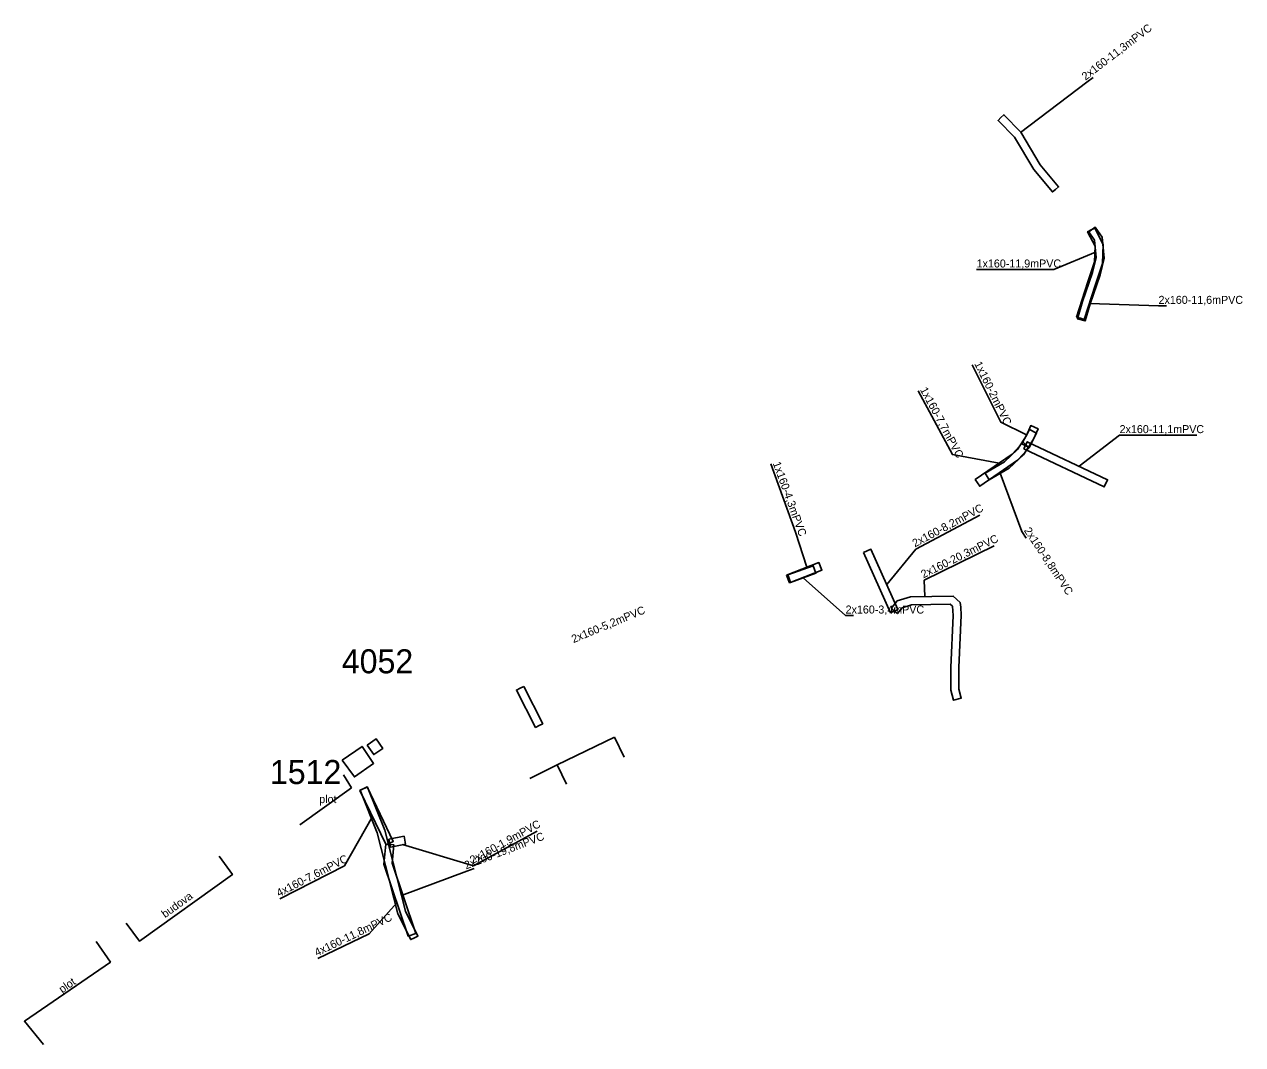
# Model space of a CAD drawing. Extents: x -743932 to -743780, y -1055899 to -1055771.
import ezdxf

# ---------------------------------------------------------------- set-up
doc = ezdxf.new("R2010")
doc.units = 0
for name, color, linetype in [('Chránička', 7, 'Continuous'), ('ST_CHRANICKA_POPIS', 7, 'Continuous'), ('ST_OBECNA_STAVBA', 7, 'Continuous'), ('ST_OBECNA_STAVBA_POPIS', 7, 'Continuous'), ('ST_TRAFOSTANICE_POPIS', 7, 'Continuous'), ('TS_RS_R', 7, 'Continuous')]:
    doc.layers.add(name, color=color, linetype=linetype)

msp = doc.modelspace()

# ---------------------------------------------------------------- linework, layer by layer
at = {"layer": 'Chránička'}
for points in [[(-743803.15, -1055791.87), (-743803.534, -1055792.19), (-743805.869, -1055789.39), (-743808.279, -1055785.346), (-743810.319, -1055783.248), (-743809.96, -1055782.9), (-743809.601, -1055782.552), (-743807.481, -1055784.734), (-743805.051, -1055788.81), (-743802.766, -1055791.55), (-743803.15, -1055791.87)], [(-743800.03, -1055807.96), (-743800.507, -1055807.809), (-743799.116, -1055803.415), (-743798.287, -1055800.929), (-743798.205, -1055798.952), (-743799.134, -1055797.149), (-743798.69, -1055796.92), (-743798.246, -1055796.691), (-743797.195, -1055798.728), (-743797.293, -1055801.111), (-743798.164, -1055803.725), (-743799.553, -1055808.111), (-743800.03, -1055807.96)], [(-743799.006, -1055797.151), (-743798.177, -1055796.589), (-743797.326, -1055797.844), (-743797.065, -1055800.454), (-743797.562, -1055802.541), (-743798.835, -1055806.162), (-743799.451, -1055808.299), (-743800.411, -1055808.021), (-743799.788, -1055805.858), (-743798.521, -1055802.259), (-743798.078, -1055800.386), (-743798.297, -1055798.196), (-743799.006, -1055797.151)], [(-743811.7, -1055827.72), (-743811.954, -1055827.289), (-743809.541, -1055825.867), (-743807.907, -1055824.347), (-743806.783, -1055822.594), (-743806.249, -1055821.361), (-743805.79, -1055821.56), (-743805.331, -1055821.759), (-743805.897, -1055823.066), (-743807.133, -1055824.993), (-743808.939, -1055826.673), (-743811.446, -1055828.151), (-743811.7, -1055827.72)], [(-743806.393, -1055821.829), (-743805.507, -1055822.293), (-743806.457, -1055824.103), (-743807.343, -1055823.639), (-743806.393, -1055821.829)], [(-743807.185, -1055823.449), (-743806.449, -1055824.128), (-743807.898, -1055825.698), (-743812.614, -1055828.931), (-743813.18, -1055828.106), (-743808.556, -1055824.938), (-743807.185, -1055823.449)], [(-743807.113, -1055824.282), (-743806.687, -1055823.378), (-743796.637, -1055828.118), (-743797.063, -1055829.022), (-743807.113, -1055824.282)], [(-743827.126, -1055837.215), (-743826.214, -1055836.805), (-743822.834, -1055844.315), (-743823.746, -1055844.725), (-743827.126, -1055837.215)], [(-743836.747, -1055840.055), (-743832.707, -1055838.465), (-743832.341, -1055839.395), (-743836.381, -1055840.985), (-743836.747, -1055840.055)], [(-743836.44, -1055840.47), (-743836.608, -1055839.999), (-743833.408, -1055838.859), (-743833.24, -1055839.33), (-743833.072, -1055839.801), (-743836.272, -1055840.941), (-743836.44, -1055840.47)], [(-743823.681, -1055844.208), (-743822.915, -1055843.248), (-743821.28, -1055842.738), (-743815.929, -1055842.642), (-743815.07, -1055843.456), (-743814.98, -1055844.053), (-743814.919, -1055845.048), (-743815.23, -1055851.583), (-743815.24, -1055854.272), (-743814.928, -1055855.385), (-743815.892, -1055855.655), (-743816.24, -1055854.408), (-743816.23, -1055851.557), (-743815.921, -1055845.072), (-743816.03, -1055843.924), (-743816.311, -1055843.658), (-743821.14, -1055843.742), (-743822.325, -1055844.112), (-743822.899, -1055844.832), (-743823.681, -1055844.208)], [(-743869.59, -1055853.93), (-743867.21, -1055858.6), (-743867.66, -1055858.83), (-743868.11, -1055859.06), (-743870.49, -1055854.39), (-743870.04, -1055854.16), (-743869.59, -1055853.93)], [(-743890.051, -1055866.916), (-743889.149, -1055866.484), (-743885.879, -1055873.294), (-743886.781, -1055873.726), (-743890.051, -1055866.916)], [(-743883.25, -1055885.33), (-743883.697, -1055885.553), (-743885.301, -1055882.336), (-743887.896, -1055872.206), (-743890.034, -1055866.866), (-743889.57, -1055866.68), (-743889.106, -1055866.494), (-743886.944, -1055871.894), (-743884.359, -1055881.984), (-743882.803, -1055885.107), (-743883.25, -1055885.33)], [(-743886.431, -1055873.02), (-743884.541, -1055872.63), (-743884.339, -1055873.61), (-743886.229, -1055874), (-743886.431, -1055873.02)], [(-743886.828, -1055873.619), (-743885.832, -1055873.707), (-743886.033, -1055875.992), (-743883.076, -1055884.793), (-743884.024, -1055885.111), (-743887.047, -1055876.113), (-743886.828, -1055873.619)]]:
    msp.add_lwpolyline(points, close=True, dxfattribs=at)
at = {"layer": 'ST_CHRANICKA_POPIS'}
for points in [[(-743807.517, -1055784.782), (-743799.247, -1055778.496), (-743798.451, -1055777.891)], [(-743813.007, -1055801.869), (-743803.353, -1055801.869), (-743798.145, -1055799.709)], [(-743798.872, -1055806.102), (-743790.276, -1055806.41), (-743789.276, -1055806.41)], [(-743813.552, -1055813.753), (-743809.993, -1055820.951), (-743806.755, -1055822.519)], [(-743820.328, -1055817), (-743816.035, -1055824.978), (-743810.174, -1055826.047)], [(-743800.213, -1055826.431), (-743795.142, -1055822.553), (-743785.488, -1055822.553)], [(-743838.721, -1055826.146), (-743835.635, -1055834.663), (-743834.205, -1055839.054)], [(-743810.061, -1055827.317), (-743807.351, -1055834.603), (-743806.797, -1055835.436)], [(-743824.239, -1055841.192), (-743820.589, -1055836.799), (-743812.598, -1055832.531)], [(-743819.463, -1055842.705), (-743819.55, -1055840.674), (-743810.8, -1055836.383)], [(-743834.672, -1055840.371), (-743829.372, -1055845.077), (-743828.372, -1055845.077)], [(-743900.044, -1055880.47), (-743891.983, -1055876.337), (-743888.487, -1055870.173)], [(-743884.711, -1055873.687), (-743875.856, -1055876.344), (-743867.909, -1055871.994)], [(-743884.862, -1055880.055), (-743876.69, -1055877.019), (-743875.756, -1055876.663)], [(-743895.326, -1055887.891), (-743888.914, -1055884.805), (-743885.422, -1055880.95)]]:
    msp.add_lwpolyline(points, dxfattribs=at)
at = {"layer": 'ST_OBECNA_STAVBA'}
for p, q in [((-743858.23, -1055860.25), (-743857.04, -1055862.75)), ((-743865.41, -1055863.74), (-743868.84, -1055865.43)), ((-743891.11, -1055866.61), (-743892.08, -1055864.97)), ((-743891.11, -1055866.61), (-743897.56, -1055871.21))]:
    msp.add_line(p, q, dxfattribs=at)
for points in [[(-743858.23, -1055860.25), (-743865.41, -1055863.74), (-743864.25, -1055866.12)], [(-743919.26, -1055883.48), (-743917.57, -1055885.75), (-743905.97, -1055877.42), (-743907.62, -1055875.12)], [(-743929.59, -1055898.66), (-743931.97, -1055895.74), (-743921.23, -1055888.36), (-743923, -1055885.78)]]:
    msp.add_lwpolyline(points, dxfattribs=at)
at = {"layer": 'TS_RS_R'}
for points in [[(-743889.13, -1055861.27), (-743888.01, -1055860.49), (-743887.19, -1055861.68), (-743888.32, -1055862.44), (-743889.13, -1055861.27)], [(-743892.25, -1055863.16), (-743889.78, -1055861.42), (-743888.35, -1055863.54), (-743890.73, -1055865.24), (-743892.25, -1055863.16)]]:
    msp.add_lwpolyline(points, close=True, dxfattribs=at)

# ---------------------------------------------------------------- texts
at = {"layer": 'ST_CHRANICKA_POPIS'}
for s, rotation, p in [('2x160-11,3mPVC', 37.27885, (-743799.399, -1055778.297)), ('1x160-2mPVC', 296.30776, (-743813.328, -1055813.643)), ('1x160-7,7mPVC', 298.28113, (-743820.107, -1055816.882)), ('1x160-4,3mPVC', 289.92201, (-743838.486, -1055826.061)), ('2x160-8,2mPVC', 28.10692, (-743820.706, -1055836.579)), ('2x160-20,3mPVC', 26.11809, (-743819.66, -1055840.449)), ('2x160-8,8mPVC', 303.62452, (-743807.143, -1055834.465)), ('2x160-5,2mPVC', 22.58983, (-743863.365, -1055848.53)), ('2x160-1,9mPVC', 28.70069, (-743875.976, -1055876.125)), ('2x200-19,8mPVC', 20.86577, (-743876.779, -1055876.785)), ('4x160-7,6mPVC', 27.14561, (-743900.158, -1055880.247)), ('4x160-11,8mPVC', 25.70413, (-743895.434, -1055887.666))]:
    msp.add_text(s, height=1, rotation=rotation, dxfattribs=at).set_placement(p)
for s, p in [('1x160-11,9mPVC', (-743813.007, -1055801.619)), ('2x160-11,6mPVC', (-743790.276, -1055806.16)), ('2x160-11,1mPVC', (-743795.142, -1055822.303)), ('2x160-3,4mPVC', (-743829.372, -1055844.827))]:
    msp.add_text(s, height=1, dxfattribs=at).set_placement(p)
at = {"layer": 'ST_OBECNA_STAVBA_POPIS'}
msp.add_text('plot', height=1, dxfattribs=at).set_placement((-743895.13, -1055868.5))
for s, rotation, p in [('budova', 35.71972, (-743914.395, -1055882.88)), ('plot', 34.46684, (-743927.245, -1055892.271))]:
    msp.add_text(s, height=1, rotation=rotation, dxfattribs=at).set_placement(p)
at = {"layer": 'ST_TRAFOSTANICE_POPIS'}
for s, p in [('4052', (-743892.314, -1055852.293)), ('1512', (-743901.293, -1055866.121))]:
    msp.add_text(s, height=3, dxfattribs=at).set_placement(p)

doc.saveas('drawing.dxf')
